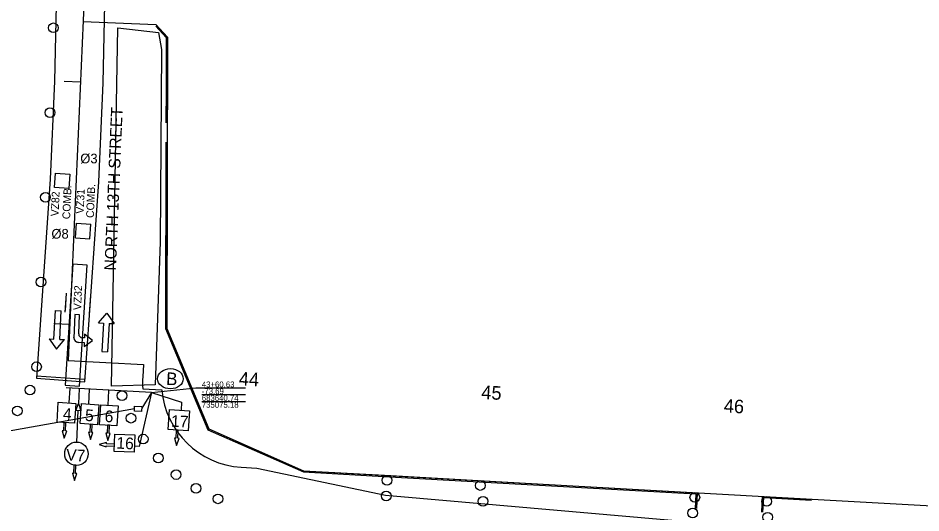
# Model space of a CAD drawing. Extents: x 679444 to 687671, y 733868 to 736107.
# Drawn here: x 683585.7 to 683957.9, y 735025.5 to 735229.7 of the extents above; entities that cross this region are included whole.
import ezdxf

# ---------------------------------------------------------------- set-up
doc = ezdxf.new("R2010")
doc.units = 0
for name, color, linetype in [('$', 7, 'Continuous'), ('Clipping Boundary', 7, 'Continuous'), ('Level 53', 7, 'Continuous'), ('MOT Stage 1', 7, 'Continuous'), ('MOT Stage 1 Lanes', 7, 'Continuous'), ('R_Horz Alg Annot', 7, 'Continuous'), ('R_Horz Alg Station', 7, 'Continuous'), ('R_TYPE_A_CURB', 7, 'Continuous'), ('RW-EX', 7, 'Continuous'), ('RW-PR', 7, 'Continuous'), ('SIGNAL-EX', 7, 'Continuous'), ('SIGNAL-PLAN VIEW LABLES', 7, 'Continuous'), ('TITEXT', 7, 'Continuous'), ('Video-Zones-pr', 7, 'Continuous')]:
    doc.layers.add(name, color=color, linetype=linetype)

# ---------------------------------------------------------------- blocks, each defined once
blk = doc.blocks.new('BAREL_1615')
at = {"layer": 'MOT Stage 1'}
blk.add_circle((0, 0.01), 2.88, dxfattribs=at)
blk = doc.blocks.new('BAREL_1616')
at = {"layer": 'MOT Stage 1'}
blk.add_circle((0, 0.01), 2.88, dxfattribs=at)
blk = doc.blocks.new('BAREL_1617')
at = {"layer": 'MOT Stage 1'}
blk.add_circle((0, 0.01), 2.88, dxfattribs=at)
blk = doc.blocks.new('BAREL_1618')
at = {"layer": 'MOT Stage 1'}
blk.add_circle((0, 0.01), 2.88, dxfattribs=at)
blk = doc.blocks.new('BAREL_1652')
at = {"layer": 'MOT Stage 1'}
blk.add_circle((0, 0.01), 2.88, dxfattribs=at)
blk = doc.blocks.new('BAREL_1653')
at = {"layer": 'MOT Stage 1'}
blk.add_circle((0, 0.01), 2.88, dxfattribs=at)
blk = doc.blocks.new('BAREL_1654')
at = {"layer": 'MOT Stage 1'}
blk.add_circle((0, 0.01), 2.88, dxfattribs=at)
blk = doc.blocks.new('BAREL_1655')
at = {"layer": 'MOT Stage 1'}
blk.add_circle((0, 0.01), 2.88, dxfattribs=at)
blk = doc.blocks.new('BAREL_1656')
at = {"layer": 'MOT Stage 1'}
blk.add_circle((0, 0.01), 2.88, dxfattribs=at)
blk = doc.blocks.new('BAREL_1657')
at = {"layer": 'MOT Stage 1'}
blk.add_circle((0, 0.01), 2.88, dxfattribs=at)
blk = doc.blocks.new('BAREL_1658')
at = {"layer": 'MOT Stage 1'}
blk.add_circle((0, 0.01), 2.88, dxfattribs=at)
blk = doc.blocks.new('SARROW_205')
at = {"layer": 'MOT Stage 1'}
for p, q in [((-6, -29.42), (-6, 0)), ((0, 0), (-6, 0)), ((0, -29.42), (0, 0)), ((-6, -29.42), (-11, -29.42)), ((-3, -39.81), (-11, -29.42)), ((5, -29.42), (-3, -39.81)), ((5, -29.42), (0, -29.42))]:
    blk.add_line(p, q, dxfattribs=at)
blk = doc.blocks.new('SARROW_206')
at = {"layer": 'MOT Stage 1'}
for p, q in [((-6, -29.42), (-6, 0)), ((0, 0), (-6, 0)), ((0, -29.42), (0, 0)), ((-6, -29.42), (-11, -29.42)), ((-3, -39.81), (-11, -29.42)), ((5, -29.42), (-3, -39.81)), ((5, -29.42), (0, -29.42))]:
    blk.add_line(p, q, dxfattribs=at)
blk = doc.blocks.new('BAREL_1704')
at = {"layer": 'MOT Stage 1'}
blk.add_circle((0, 0.01), 2.88, dxfattribs=at)
blk = doc.blocks.new('BAREL_1705')
at = {"layer": 'MOT Stage 1'}
blk.add_circle((0, 0.01), 2.88, dxfattribs=at)
blk = doc.blocks.new('BAREL_1706')
at = {"layer": 'MOT Stage 1'}
blk.add_circle((0, 0.01), 2.88, dxfattribs=at)
blk = doc.blocks.new('BAREL_1707')
at = {"layer": 'MOT Stage 1'}
blk.add_circle((0, 0.01), 2.88, dxfattribs=at)
blk = doc.blocks.new('BAREL_1713')
at = {"layer": 'MOT Stage 1'}
blk.add_circle((0, 0.01), 2.88, dxfattribs=at)
blk = doc.blocks.new('BAREL_1714')
at = {"layer": 'MOT Stage 1'}
blk.add_circle((0, 0.01), 2.88, dxfattribs=at)
blk = doc.blocks.new('BAREL_1715')
at = {"layer": 'MOT Stage 1'}
blk.add_circle((0, 0.01), 2.88, dxfattribs=at)
blk = doc.blocks.new('BAREL_1716')
at = {"layer": 'MOT Stage 1'}
blk.add_circle((0, 0.01), 2.88, dxfattribs=at)
blk = doc.blocks.new('BAREL_1717')
at = {"layer": 'MOT Stage 1'}
blk.add_circle((0, 0.01), 2.88, dxfattribs=at)
blk = doc.blocks.new('BAREL_1718')
at = {"layer": 'MOT Stage 1'}
blk.add_circle((0, 0.01), 2.88, dxfattribs=at)
blk = doc.blocks.new('BAREL_1719')
at = {"layer": 'MOT Stage 1'}
blk.add_circle((0, 0.01), 2.88, dxfattribs=at)

msp = doc.modelspace()

# ---------------------------------------------------------------- linework, layer by layer
at = {"layer": 'Clipping Boundary'}
msp.add_lwpolyline([(683624.26, 735077.79), (683626.77, 735225.66), (683643.57, 735223.66), (683644.8, 735216.71), (683644.3, 735137.31), (683642.23, 735078.38)], close=True, dxfattribs=at)
at = {"layer": 'Level 53'}
for p, q in [((683605.17, 735108.34), (683605.71, 735116.09)), ((683605.21, 735108.97), (683605.71, 735116.11)), ((683615.14, 735107.49), (683615.69, 735115.39))]:
    msp.add_line(p, q, dxfattribs=at)
at = {"layer": 'MOT Stage 1'}
for points in [[(683609.12, 735107.33), (683608.69, 735097.56), (683608.71, 735097.88)], [(683610.7, 735099.39), (683611.04, 735107.24), (683609.12, 735107.33)], [(683610.54, 735095.88), (683610.22, 735095.89), (683612.97, 735095.77), (683612.9, 735094.17), (683616.34, 735096.59), (683613.13, 735099.29), (683613.06, 735097.69), (683612.23, 735097.72)]]:
    msp.add_lwpolyline(points, dxfattribs=at)
for centre, radius in [((683610.63, 735097.79), 1.92), ((683612.29, 735099.32), 1.6)]:
    msp.add_arc(centre, radius, 177.5178, 267.5178, dxfattribs=at)
at = {"layer": 'MOT Stage 1 Lanes'}
for points in [[(683604.91, 735398.45), (683600.74, 735203.61), (683598.98, 735163.25), (683593.24, 735081.04), (683613.19, 735079.65), (683618.95, 735162.12), (683620.73, 735202.96), (683624.91, 735398.02)], [(683593.31, 735082.04), (683613.26, 735080.64)]]:
    msp.add_lwpolyline(points, dxfattribs=at)
at = {"layer": 'R_Horz Alg Annot'}
for p, q in [((683661.43, 735077.12), (683679.46, 735077.12)), ((683661.43, 735074.32), (683679.46, 735074.32)), ((683661.43, 735071.52), (683679.46, 735071.52))]:
    msp.add_line(p, q, dxfattribs=at)
msp.add_lwpolyline([(683640.74, 735075.18), (683659.03, 735077.12), (683661.43, 735077.12)], dxfattribs=at)
at = {"layer": 'R_Horz Alg Station'}
for points in [[(683604.74, 735203.6), (683611.4, 735203.31)], [(683600.38, 735103.7), (683607.04, 735103.4)]]:
    msp.add_lwpolyline(points, dxfattribs=at)
at = {"layer": 'R_TYPE_A_CURB'}
for points in [[(683642.47, 735226.98), (683647.24, 735221.76), (683647.2, 735200.49)], [(683642.44, 735226.27), (683646.74, 735221.57), (683646.7, 735200.49)], [(683646.7, 735200.49), (683646.67, 735186.44)], [(683647.2, 735200.49), (683647.17, 735186.44)], [(683646.66, 735178.44), (683646.51, 735101.56), (683663.93, 735059.77), (683703.29, 735042.44), (683738.83, 735040.46), (683775.77, 735038.39)], [(683647.16, 735178.44), (683647.01, 735101.66), (683664.31, 735060.15), (683703.41, 735042.94), (683739.35, 735040.93), (683775.3, 735038.92)], [(683775.3, 735038.92), (683865.66, 735033.86), (683865.29, 735027.37)], [(683775.77, 735038.39), (683865.13, 735033.39), (683864.79, 735027.4)], [(683892.25, 735025.86), (683892.61, 735032.35), (683912.75, 735031.23)], [(683892.75, 735025.84), (683893.09, 735031.83), (683912.72, 735030.73)]]:
    msp.add_lwpolyline(points, dxfattribs=at)
at = {"layer": 'RW-EX'}
for p, q in [((683621.76, 735440.48), (683606.39, 735088.43)), ((683606.39, 735088.43), (683637.37, 735086.69)), ((683637.37, 735086.69), (683637.09, 735081.7)), ((683637.11, 735076.69), (683644.97, 735076.25)), ((683677.64, 735044.35), (683684.1, 735043.94)), ((683684.1, 735043.94), (683737.17, 735032.78)), ((683737.17, 735032.78), (683956.81, 735013.74))]:
    msp.add_line(p, q, dxfattribs=at)
for centre, radius, start, end in [((683680.03, 735079.3), 43, 176.7989, 183.4763), ((683679.84, 735079.28), 35, 184.9566, 266.3951)]:
    msp.add_arc(centre, radius, start, end, dxfattribs=at)
at = {"layer": 'RW-PR'}
for points in [[(683612.49, 735228.29), (683642.47, 735226.98), (683647.24, 735221.76), (683647.01, 735101.66), (683664.31, 735060.15)], [(683664.31, 735060.15), (683703.41, 735042.94), (683910.62, 735031.35), (684095.94, 735020.98), (684195.75, 735015.4)]]:
    msp.add_lwpolyline(points, dxfattribs=at)
at = {"layer": 'SIGNAL-EX'}
msp.add_line((683640.74, 735075.18), (683605.56, 735077.1), dxfattribs=at)
for points in [[(683640.74, 735075.18), (683636.7, 735068.73)], [(683633.68, 735068.46), (683557.16, 735054.83)]]:
    msp.add_lwpolyline(points, dxfattribs=at)
msp.add_lwpolyline([(683633.73, 735069.49), (683636.72, 735069.35), (683636.63, 735067.36), (683633.64, 735067.5)], close=True, dxfattribs=at)
at = {"layer": 'SIGNAL-PLAN VIEW LABLES'}
for points in [[(683606.99, 735077.02), (683606.68, 735070.89)], [(683610.86, 735076.77), (683610.62, 735070.65)], [(683614.98, 735076.51), (683614.66, 735070.41)], [(683622.96, 735076.01), (683622.65, 735069.98)], [(683640.74, 735075.18), (683635.68, 735052.96), (683633.65, 735053.07)], [(683640.74, 735075.18), (683653.12, 735071.23), (683652.95, 735067.86)], [(683610.3, 735067.7), (683609.79, 735054.76)], [(683604.44, 735059.37), (683603.93, 735059.4), (683604.7, 735056.4), (683605.78, 735059.3), (683605.28, 735059.33), (683605.45, 735062.68), (683604.61, 735062.73), (683604.44, 735059.37)], [(683604.61, 735062.73), (683604.44, 735059.37), (683603.93, 735059.4), (683604.7, 735056.4), (683605.78, 735059.3), (683605.28, 735059.33), (683605.45, 735062.68)], [(683615.22, 735058.74), (683614.72, 735058.77), (683615.49, 735055.77), (683616.56, 735058.67), (683616.06, 735058.7), (683616.23, 735062.05), (683615.39, 735062.1), (683615.22, 735058.74)], [(683615.39, 735062.1), (683615.22, 735058.74), (683614.72, 735058.77), (683615.49, 735055.77), (683616.56, 735058.67), (683616.06, 735058.7), (683616.23, 735062.05)], [(683622.37, 735058.35), (683621.87, 735058.38), (683622.64, 735055.39), (683623.71, 735058.29), (683623.21, 735058.31), (683623.38, 735061.67), (683622.54, 735061.71), (683622.37, 735058.35)], [(683622.54, 735061.71), (683622.37, 735058.35), (683621.87, 735058.38), (683622.64, 735055.39), (683623.71, 735058.29), (683623.21, 735058.31), (683623.38, 735061.67)], [(683650.71, 735056.34), (683650.2, 735056.37), (683650.97, 735053.37), (683652.05, 735056.27), (683651.55, 735056.3), (683651.72, 735059.65), (683650.88, 735059.7), (683650.71, 735056.34)], [(683650.88, 735059.7), (683650.71, 735056.34), (683650.2, 735056.37), (683650.97, 735053.37), (683652.05, 735056.27), (683651.55, 735056.3), (683651.72, 735059.65)], [(683622.08, 735054.08), (683622.11, 735054.59), (683619.11, 735053.81), (683622.01, 735052.74), (683622.04, 735053.24), (683625.39, 735053.07), (683625.44, 735053.91), (683622.08, 735054.08)], [(683625.44, 735053.91), (683622.08, 735054.08), (683622.11, 735054.59), (683619.11, 735053.81), (683622.01, 735052.74), (683622.04, 735053.24), (683625.39, 735053.07)], [(683608.58, 735041.83), (683608.08, 735041.85), (683608.91, 735038.87), (683609.93, 735041.79), (683609.42, 735041.8), (683609.53, 735045.16), (683608.69, 735045.19), (683608.58, 735041.83)], [(683608.69, 735045.19), (683608.58, 735041.83), (683608.08, 735041.85), (683608.91, 735038.87), (683609.93, 735041.79), (683609.42, 735041.8), (683609.53, 735045.16)]]:
    msp.add_lwpolyline(points, dxfattribs=at)
for points in [[(683608.93, 735062.48), (683601.8, 735062.9), (683602.29, 735071.15), (683609.48, 735070.72)], [(683610.62, 735070.65), (683611.54, 735067.64), (683609.46, 735067.74)], [(683618.43, 735061.92), (683611.31, 735062.34), (683611.8, 735070.59), (683618.99, 735070.16)], [(683626.42, 735061.49), (683619.3, 735061.91), (683619.79, 735070.16), (683626.98, 735069.73)], [(683655.8, 735059.41), (683647.57, 735059.9), (683648.06, 735068.15), (683656.35, 735067.65)], [(683625.32, 735050.9), (683625.57, 735058.03), (683633.83, 735057.74), (683633.58, 735050.54)]]:
    msp.add_lwpolyline(points, close=True, dxfattribs=at)
msp.add_circle((683609.76, 735049.91), 4.85, dxfattribs=at)
msp.add_ellipse((683648.5, 735080.87), major_axis=(-5.27, 0), ratio=0.790685, dxfattribs=at)
at = {"layer": 'Video-Zones-pr'}
for points in [[(683606.65, 735159.29), (683600.67, 735159.71), (683601.09, 735165.7), (683607.07, 735165.28), (683606.65, 735159.29)], [(683609.32, 735139.06), (683609.73, 735145.05)], [(683609.73, 735145.05), (683615.72, 735144.63)], [(683615.3, 735138.64), (683615.72, 735144.63)], [(683609.32, 735139.06), (683615.3, 735138.64)]]:
    msp.add_lwpolyline(points, dxfattribs=at)
msp.add_lwpolyline([(683608.23, 735128.09), (683605.07, 735078.19), (683611.06, 735077.81), (683614.21, 735127.71)], close=True, dxfattribs=at)

# ---------------------------------------------------------------- block references
at = {"layer": 'MOT Stage 1'}
for name, p, xscale, yscale, rotation in [('BAREL_1719', (683600.25, 735225.63), 0.6945420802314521, 0.6945420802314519, 87.04179557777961), ('BAREL_1718', (683598.85, 735190.66), 0.6945420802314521, 0.6945420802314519, 87.04179557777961), ('BAREL_1717', (683596.99, 735155.71), 0.6945420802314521, 0.6945420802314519, 87.04179557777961), ('BAREL_1716', (683595.11, 735120.76), 0.6945420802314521, 0.6945420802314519, 87.04179557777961), ('SARROW_205', (683601.06, 735108.99), 0.4000000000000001, -0.4000000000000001, 177.22923073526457), ('SARROW_206', (683620.19, 735092.11), 0.3999999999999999, 0.3999999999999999, 176.69984902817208), ('BAREL_1715', (683593.31, 735085.8), 0.6945420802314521, 0.6945420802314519, 87.04179557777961), ('BAREL_1714', (683590.6, 735076.18), 0.6945420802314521, 0.6945420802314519, 87.04179557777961), ('BAREL_1658', (683628.56, 735073.9), 0.6945420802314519, 0.694542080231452, 102.17652807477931), ('BAREL_1713', (683585.42, 735067.62), 0.6945420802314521, 0.6945420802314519, 87.04179557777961), ('BAREL_1657', (683632.27, 735064.61), 0.6945420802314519, 0.694542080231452, 102.17652807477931), ('BAREL_1656', (683637.29, 735055.97), 0.6945420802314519, 0.694542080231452, 102.17652807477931), ('BAREL_1655', (683643.51, 735048.14), 0.6945420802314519, 0.694542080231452, 102.17652807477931), ('BAREL_1654', (683650.85, 735041.34), 0.6945420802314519, 0.694542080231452, 102.17652807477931), ('BAREL_1704', (683737.8, 735038.96), 0.6945420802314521, 0.6945420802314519, 87.04179557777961), ('BAREL_1653', (683659.08, 735035.66), 0.6945420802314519, 0.694542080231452, 102.17652807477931), ('BAREL_1705', (683776.24, 735036.83), 0.6945420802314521, 0.6945420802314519, 87.04179557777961), ('BAREL_1652', (683668.09, 735031.32), 0.6945420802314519, 0.694542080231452, 102.17652807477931), ('BAREL_1615', (683737.45, 735032.53), 0.6945420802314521, 0.6945420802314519, 87.04179557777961), ('BAREL_1706', (683864.67, 735031.93), 0.6945420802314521, 0.6945420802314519, 87.04179557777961), ('BAREL_1616', (683777.38, 735030.31), 0.6945420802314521, 0.6945420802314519, 87.04179557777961), ('BAREL_1707', (683894.24, 735030.29), 0.6945420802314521, 0.6945420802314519, 87.04179557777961), ('BAREL_1617', (683863.75, 735025.46), 0.6945420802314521, 0.6945420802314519, 87.04179557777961), ('BAREL_1618', (683894.7, 735023.75), 0.6945420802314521, 0.6945420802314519, 87.04179557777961)]:
    msp.add_blockref(name, p, dxfattribs=dict(at, xscale=xscale, yscale=yscale, rotation=rotation))

# ---------------------------------------------------------------- texts
at = {"layer": '$'}
for s, height, rotation, p in [('NORTH 13TH STREET', 4.8, 87.5995, (683626.03, 735125.41)), ('COMB.', 3.2, 87.5006, (683607.12, 735146.63)), ('COMB.', 3.2, 87.5006, (683616.91, 735147.15)), ('VZ82', 3.2, 87.5006, (683602.37, 735147.82)), ('VZ31', 3.2, 87.5006, (683612.72, 735148.86)), ('VZ32', 3.2, 87.5006, (683611.65, 735109.11)), ('44', 5.6, 357.0415, (683676.59, 735078.14)), ('45', 5.6, 357.0415, (683776.54, 735072.55)), ('46', 5.6, 357.0415, (683876.49, 735066.96))]:
    msp.add_text(s, height=height, rotation=rotation, dxfattribs=at).set_placement(p)
at = {"layer": 'R_Horz Alg Annot'}
for s, p in [('43+60.63', (683661.43, 735077.32)), ('-73.69', (683661.43, 735074.52)), ('683640.74', (683661.43, 735071.72)), ('735075.18', (683661.43, 735068.92))]:
    msp.add_text(s, height=2.4, dxfattribs=at).set_placement(p)
at = {"layer": 'SIGNAL-PLAN VIEW LABLES'}
for s, height, p in [('B', 5.2, (683646.63, 735078.36)), ('4', 4.8, (683604.1, 735064.03)), ('5', 4.8, (683613.2, 735063.48)), ('6', 4.8, (683621.3, 735063.05)), ('17', 4.8, (683648.66, 735061.09)), ('16', 4.8, (683626.15, 735052.07)), ('V7', 4.8, (683605.42, 735047.13))]:
    msp.add_text(s, height=height, rotation=357.0414, dxfattribs=at).set_placement(p)
at = {"layer": 'TITEXT'}
for s, p in [('%%C3', (683611.34, 735169.72)), ('%%C8', (683599.44, 735138.66))]:
    msp.add_text(s, height=4, dxfattribs=at).set_placement(p)

doc.saveas('drawing.dxf')
